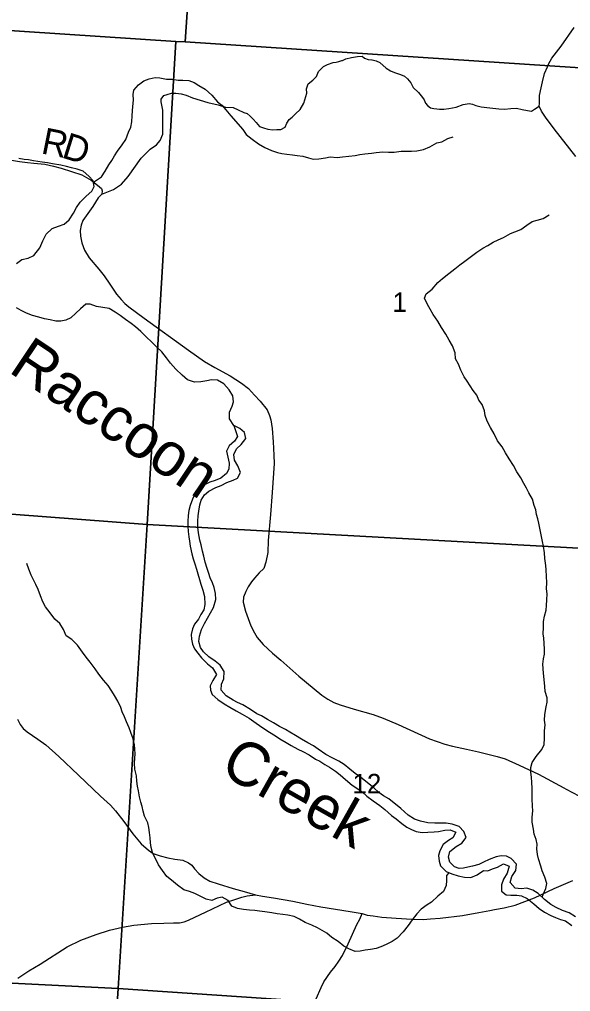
# Model space of a CAD drawing. Extents: x 0 to 34, y 0 to 22.
# Drawn here: x 25.453 to 26.642, y 16.992 to 19.088 of the extents above; entities that cross this region are included whole.
import ezdxf

# ---------------------------------------------------------------- set-up
doc = ezdxf.new("R2010")
doc.units = 0
for name, color, linetype in [('GM_X_Major_River', 7, 'Continuous'), ('GM_X_Major_River_Text', 7, 'Continuous'), ('GM_X_Minor_River', 7, 'Continuous'), ('GM_X_Section', 7, 'Continuous'), ('GM_X_Section_Text', 7, 'Continuous'), ('GM_X_State_Route', 7, 'Continuous'), ('GM_X_Township_Road', 7, 'Continuous'), ('GM_X_Township_Road_Text', 7, 'Continuous')]:
    doc.layers.add(name, color=color, linetype=linetype)

msp = doc.modelspace()

# ---------------------------------------------------------------- linework, layer by layer
at = {"layer": 'GM_X_Major_River'}
for points in [[(25.4467, 18.5616), (25.4589, 18.5707), (25.4721, 18.5732), (25.4843, 18.5792), (25.4973, 18.5958), (25.5035, 18.6109), (25.5108, 18.6249), (25.5242, 18.6373), (25.5378, 18.6422), (25.55, 18.6466), (25.5607, 18.6564), (25.5703, 18.6704), (25.5764, 18.6828), (25.5841, 18.6945), (25.5971, 18.7073), (25.6097, 18.7183), (25.6143, 18.7281), (25.6128, 18.7399), (25.6034, 18.7505), (25.5906, 18.7609), (25.5781, 18.7655), (25.566, 18.7683), (25.5546, 18.771), (25.5425, 18.7741), (25.5247, 18.7769), (25.5137, 18.7789), (25.5023, 18.7805), (25.4929, 18.7817), (25.4834, 18.7837), (25.4728, 18.7857), (25.4633, 18.7865), (25.452, 18.7885)], [(25.9162, 18.2126), (25.9068, 18.2267), (25.9069, 18.2411), (25.9123, 18.2539), (25.9154, 18.2638), (25.9136, 18.2767), (25.9057, 18.2893), (25.894, 18.3026), (25.8804, 18.3103), (25.8676, 18.3112), (25.8577, 18.309), (25.8448, 18.3064), (25.8311, 18.3058), (25.8163, 18.3112), (25.8047, 18.3211), (25.7907, 18.3341), (25.779, 18.3467), (25.7704, 18.3582), (25.7606, 18.3712), (25.7493, 18.3819), (25.7387, 18.3926), (25.7271, 18.404), (25.715, 18.4155), (25.7041, 18.4251), (25.6943, 18.4327), (25.6822, 18.4415), (25.6708, 18.4496), (25.6599, 18.4573), (25.6467, 18.4646), (25.633, 18.4673), (25.6194, 18.4689), (25.6061, 18.4743), (25.5963, 18.474), (25.5848, 18.4639), (25.5749, 18.4545), (25.5646, 18.4447), (25.5536, 18.4398), (25.5426, 18.4373), (25.5316, 18.4377), (25.5194, 18.4405), (25.5077, 18.4428), (25.4952, 18.4459), (25.4819, 18.4495), (25.4687, 18.4545), (25.457, 18.4603), (25.4468, 18.466)], [(26.4209, 17.2596), (26.4114, 17.2577), (26.4019, 17.2571), (26.392, 17.2609), (26.3822, 17.2709), (26.3789, 17.2811), (26.382, 17.294), (26.3954, 17.3042), (26.4079, 17.3113), (26.4175, 17.3237), (26.4119, 17.337), (26.4017, 17.3474), (26.3873, 17.3524), (26.3741, 17.3544), (26.3623, 17.3545), (26.3494, 17.3549), (26.3342, 17.3554), (26.3183, 17.3594), (26.3058, 17.3636), (26.2919, 17.3717), (26.2764, 17.3862), (26.25, 17.4069), (26.2387, 17.4138), (26.2288, 17.4211), (26.2179, 17.4307), (26.2081, 17.4387), (26.1892, 17.454), (26.1775, 17.4621), (26.1662, 17.4713), (26.1538, 17.4812), (26.1424, 17.4885), (26.1281, 17.4954), (26.1145, 17.5028), (26.0978, 17.5143), (26.088, 17.5215), (26.0756, 17.5277), (26.062, 17.5362), (26.0487, 17.5442), (26.037, 17.5511), (26.0272, 17.5565), (26.0143, 17.5631), (26.0015, 17.5711), (25.9886, 17.5784), (25.9754, 17.5865), (25.9656, 17.5907), (25.952, 17.5996), (25.9354, 17.6099), (25.924, 17.6149), (25.9142, 17.6203), (25.8991, 17.6295), (25.8889, 17.6418), (25.889, 17.6543), (25.8944, 17.6664), (25.8953, 17.6819), (25.8866, 17.6953), (25.8753, 17.7045), (25.8621, 17.7137), (25.8504, 17.7244), (25.844, 17.7339), (25.8403, 17.7465), (25.8419, 17.7582), (25.8462, 17.7722), (25.8527, 17.7854), (25.8592, 17.7968), (25.8657, 17.8085), (25.8719, 17.8198), (25.8769, 17.8372), (25.8766, 17.8498), (25.8737, 17.8631), (25.87, 17.8733), (25.8651, 17.8836), (25.8621, 17.8931), (25.8584, 17.9042), (25.8543, 17.9175), (25.8514, 17.9304), (25.848, 17.9418), (25.8455, 17.9551), (25.8425, 17.965), (25.84, 17.9813), (25.8385, 17.9935), (25.8382, 18.0064), (25.8391, 18.0174), (25.8403, 18.028), (25.8426, 18.0416), (25.8454, 18.0518), (25.8526, 18.0628), (25.8622, 18.0711), (25.8774, 18.0789), (25.8884, 18.0834), (25.901, 18.0898), (25.9143, 18.0946), (25.9238, 18.0991), (25.9303, 18.1112), (25.9247, 18.1252), (25.9176, 18.1374), (25.9162, 18.1503), (25.9219, 18.1621), (25.9319, 18.1715), (25.9418, 18.1847), (25.9392, 18.1972), (25.9291, 18.206)], [(25.9162, 18.2126), (25.9236, 18.1886), (25.9171, 18.1784)], [(25.9291, 18.206), (25.9162, 18.2126)], [(25.9171, 18.1784), (25.9061, 18.169), (25.9003, 18.1569), (25.9029, 18.144), (25.9062, 18.1311), (25.905, 18.1186), (25.9004, 18.1087), (25.8878, 18.099), (25.8756, 18.0937), (25.8638, 18.09), (25.8524, 18.0844), (25.8398, 18.0746), (25.831, 18.0633), (25.8264, 18.0535), (25.8218, 18.0403), (25.819, 18.0289), (25.8174, 18.0187), (25.8166, 18.0054), (25.8169, 17.9955), (25.8176, 17.9841), (25.819, 17.9727), (25.8201, 17.9629), (25.8219, 17.9526), (25.8252, 17.9359), (25.8282, 17.9249), (25.8319, 17.9142), (25.8353, 17.9028), (25.8386, 17.8925), (25.8419, 17.8804), (25.8449, 17.8701), (25.849, 17.8572), (25.8527, 17.8435), (25.8537, 17.8264), (25.851, 17.8151), (25.8449, 17.8045), (25.8395, 17.7946), (25.8311, 17.7837), (25.8268, 17.7739), (25.8241, 17.7614), (25.8244, 17.7515), (25.827, 17.7412), (25.8311, 17.7306), (25.8382, 17.7211), (25.8461, 17.7111), (25.859, 17.6981), (25.8699, 17.6897), (25.8785, 17.6752), (25.8705, 17.6624), (25.8651, 17.651), (25.8658, 17.6416), (25.8695, 17.632), (25.8812, 17.6213), (25.8948, 17.6125), (25.9076, 17.6048), (25.9209, 17.5971), (25.9337, 17.5902), (25.9492, 17.581), (25.9639, 17.5703), (25.9783, 17.5607), (25.9926, 17.5507), (26.0055, 17.5434), (26.0153, 17.5369), (26.0289, 17.5284), (26.0395, 17.5223), (26.0542, 17.5146), (26.0648, 17.5092), (26.0788, 17.5023), (26.092, 17.4931), (26.1018, 17.4884), (26.112, 17.4811), (26.1226, 17.4754), (26.1355, 17.4666), (26.1453, 17.4589), (26.157, 17.4486), (26.1713, 17.4367), (26.1811, 17.4302), (26.1932, 17.4217), (26.203, 17.4133), (26.2166, 17.403), (26.2309, 17.3926), (26.2419, 17.3842), (26.2562, 17.3716), (26.2664, 17.3643), (26.2785, 17.3543), (26.289, 17.3463), (26.2989, 17.3409), (26.3095, 17.337), (26.322, 17.3347), (26.3341, 17.3357), (26.3478, 17.3364), (26.3576, 17.3371), (26.3713, 17.34), (26.3827, 17.3407), (26.3948, 17.3356), (26.3886, 17.3228), (26.3791, 17.3172), (26.3673, 17.3085), (26.36, 17.2953), (26.3577, 17.2851), (26.3587, 17.2725), (26.3621, 17.263)], [(26.653, 17.1528), (26.6391, 17.1616), (26.6247, 17.1666), (26.6111, 17.1732), (26.5997, 17.179), (26.5858, 17.1904), (26.5722, 17.2031), (26.5609, 17.2104), (26.548, 17.2146), (26.5359, 17.2132), (26.523, 17.2148), (26.512, 17.2266), (26.5155, 17.2395), (26.5244, 17.2527), (26.5256, 17.266), (26.5143, 17.2782), (26.5045, 17.2836), (26.4927, 17.2841), (26.4817, 17.2819), (26.4665, 17.2763), (26.4547, 17.2707), (26.4448, 17.2658), (26.4307, 17.2618), (26.4209, 17.2596)], [(26.3621, 17.263), (26.3738, 17.2504), (26.3859, 17.2454), (26.4002, 17.2408), (26.4139, 17.238), (26.4275, 17.2379), (26.4408, 17.2435), (26.4546, 17.2525), (26.464, 17.2517), (26.4739, 17.2561), (26.4846, 17.2602), (26.4975, 17.267), (26.51, 17.2619), (26.5054, 17.2472), (26.4977, 17.234), (26.4934, 17.2219), (26.4933, 17.2082), (26.5035, 17.2005), (26.5134, 17.1993), (26.5263, 17.1992), (26.5365, 17.198), (26.5486, 17.1926), (26.5629, 17.1807), (26.575, 17.1704), (26.5863, 17.1627), (26.6, 17.1554), (26.6098, 17.1512), (26.6204, 17.1473), (26.6317, 17.1438), (26.645, 17.1338)]]:
    msp.add_lwpolyline(points, dxfattribs=at)
at = {"layer": 'GM_X_Minor_River'}
for points in [[(25.6131, 18.7376), (25.6307, 18.7487), (25.6386, 18.7613), (25.6465, 18.7746), (25.6525, 18.7841), (25.6586, 18.7939), (25.665, 18.8042), (25.6751, 18.8179), (25.6827, 18.8296), (25.6887, 18.8452), (25.6936, 18.8558), (25.6958, 18.8672), (25.6965, 18.8805), (25.6976, 18.8911), (25.6983, 18.9009), (25.6994, 18.9142), (25.699, 18.9263), (25.7005, 18.9358), (25.7103, 18.9472), (25.722, 18.956), (25.733, 18.9602), (25.7462, 18.9632), (25.7561, 18.9621), (25.7705, 18.9599), (25.7822, 18.9592), (25.7958, 18.9573), (25.806, 18.9573), (25.8185, 18.9566), (25.8303, 18.9521), (25.8405, 18.9457), (25.8538, 18.9377), (25.8682, 18.9252), (25.8804, 18.9109), (25.8903, 18.9033), (25.899, 18.8935), (25.9093, 18.8806), (25.9351, 18.8511), (25.9427, 18.8401), (25.9552, 18.8299), (25.9689, 18.8201), (25.9829, 18.8122), (25.9969, 18.8058), (26.0102, 18.8016), (26.0197, 18.799), (26.0303, 18.7979), (26.0428, 18.7964), (26.0526, 18.7949), (26.0651, 18.7934), (26.0772, 18.7897), (26.0871, 18.787), (26.0996, 18.7874), (26.1136, 18.7901), (26.1238, 18.7917), (26.1386, 18.7909), (26.1503, 18.7917), (26.1643, 18.7933), (26.1775, 18.7952), (26.1874, 18.7968), (26.1983, 18.7987), (26.2131, 18.8002), (26.2233, 18.8014), (26.2377, 18.8026), (26.2494, 18.8018), (26.2619, 18.8022), (26.2767, 18.8042), (26.2877, 18.8042), (26.2994, 18.8039), (26.3108, 18.805), (26.3251, 18.8077), (26.3391, 18.8138), (26.3539, 18.8222), (26.3648, 18.8245), (26.3773, 18.8313), (26.3894, 18.8355)], [(26.3642, 18.4241), (26.3562, 18.4377), (26.3463, 18.4521), (26.3395, 18.4635), (26.3334, 18.4733), (26.3273, 18.487), (26.3307, 18.4964), (26.3439, 18.5067), (26.3563, 18.5212), (26.3662, 18.5295), (26.3797, 18.5402), (26.3926, 18.5508), (26.4035, 18.5588), (26.4141, 18.5668), (26.4285, 18.5778), (26.4402, 18.5866), (26.4534, 18.5953), (26.464, 18.6007), (26.4753, 18.6083), (26.4863, 18.6132), (26.4976, 18.6182), (26.5127, 18.6269), (26.5225, 18.63), (26.5354, 18.6353), (26.5482, 18.6445), (26.5599, 18.6525), (26.5702, 18.6555), (26.583, 18.659), (26.5962, 18.667)], [(26.5811, 17.1948), (26.5836, 17.201), (26.5888, 17.2135), (26.5911, 17.2249), (26.5872, 17.2382), (26.5811, 17.2518), (26.5785, 17.2617), (26.5731, 17.278), (26.5708, 17.2874), (26.5696, 17.2992), (26.57, 17.3098), (26.5681, 17.3193), (26.5642, 17.3307), (26.5623, 17.3416), (26.5592, 17.3572), (26.5596, 17.3674), (26.5607, 17.3815), (26.5602, 17.3913), (26.5598, 17.4076), (26.5594, 17.4186), (26.5597, 17.4296), (26.5589, 17.4433), (26.5578, 17.4531), (26.557, 17.4653), (26.5566, 17.4751), (26.5596, 17.4854), (26.5682, 17.4983), (26.5803, 17.5135), (26.5852, 17.5241), (26.5859, 17.5381), (26.5858, 17.5541), (26.5873, 17.5669), (26.5858, 17.5768), (26.5872, 17.5889), (26.5898, 17.6056), (26.5917, 17.6155), (26.5917, 17.625), (26.5875, 17.639), (26.5867, 17.6496), (26.5851, 17.6644), (26.5839, 17.678), (26.5823, 17.6978), (26.5838, 17.7095), (26.5861, 17.719), (26.5864, 17.7296), (26.5856, 17.7429), (26.5844, 17.7535), (26.5836, 17.763), (26.584, 17.7766), (26.5843, 17.7895), (26.5858, 17.8009), (26.5899, 17.8142), (26.5903, 17.8244), (26.591, 17.8362), (26.5917, 17.8495), (26.5905, 17.8601), (26.5909, 17.8741), (26.5908, 17.8866), (26.59, 17.901), (26.5888, 17.9105), (26.5869, 17.9253), (26.5865, 17.9382), (26.5842, 17.9522), (26.5819, 17.9624), (26.5796, 17.9734), (26.5742, 18.0015), (26.5719, 18.0109), (26.5692, 18.0208), (26.5673, 18.0306), (26.5642, 18.0401), (26.56, 18.0534), (26.552, 18.067), (26.547, 18.0772), (26.5417, 18.0871), (26.5349, 18.0996), (26.5265, 18.1128), (26.5193, 18.1261), (26.5097, 18.1405), (26.5017, 18.1537), (26.4949, 18.1666), (26.4846, 18.1795), (26.4778, 18.1942), (26.4698, 18.2082), (26.4622, 18.2219), (26.4583, 18.2344), (26.4564, 18.2442), (26.4518, 18.2575), (26.4442, 18.2673), (26.4404, 18.2783), (26.432, 18.2882), (26.426, 18.298), (26.4195, 18.3078), (26.4126, 18.3177), (26.4058, 18.3321), (26.4008, 18.345), (26.3943, 18.3563), (26.3932, 18.3696), (26.3878, 18.384), (26.3802, 18.3965), (26.3734, 18.4097), (26.3642, 18.4241)], [(25.5483, 17.7722), (25.5403, 17.7854), (25.5297, 17.7945), (25.5194, 17.8081), (25.5095, 17.8214), (25.5042, 17.832), (25.4985, 17.8449), (25.4935, 17.8585), (25.4889, 17.8699), (25.484, 17.8797), (25.479, 17.8899), (25.4737, 17.9024), (25.4691, 17.9149)], [(26.3798, 17.2479), (26.3749, 17.2422), (26.3745, 17.2308), (26.3742, 17.2202), (26.3685, 17.2073), (26.3561, 17.1974), (26.3425, 17.1841), (26.3327, 17.1784), (26.3198, 17.1689), (26.3108, 17.1594), (26.301, 17.1465), (26.2919, 17.1343), (26.281, 17.1203), (26.2686, 17.107), (26.2576, 17.0997), (26.2448, 17.0933), (26.233, 17.0883), (26.2232, 17.0841), (26.2111, 17.0825), (26.1994, 17.081), (26.1888, 17.0787), (26.1778, 17.0783), (26.1638, 17.084), (26.1535, 17.0892), (26.141, 17.0994), (26.1277, 17.1081), (26.1164, 17.1176), (26.1065, 17.1232), (26.0963, 17.1293), (26.0841, 17.1346), (26.0697, 17.1402), (26.0576, 17.1478), (26.0462, 17.1534), (26.0322, 17.1561), (26.0216, 17.1575), (26.0095, 17.1594), (25.9977, 17.1613), (25.9826, 17.1635), (25.9712, 17.165), (25.9614, 17.1661), (25.9496, 17.1672), (25.9371, 17.1687), (25.9239, 17.1706), (25.9114, 17.1759), (25.9038, 17.188), (25.8905, 17.1948), (25.8799, 17.1928), (25.8686, 17.1883), (25.8564, 17.1905), (25.8432, 17.1973), (25.8318, 17.2033), (25.8204, 17.2071), (25.8079, 17.2109), (25.7943, 17.2211), (25.7817, 17.2317), (25.7715, 17.2396), (25.762, 17.2525), (25.7536, 17.265), (25.7403, 17.2915), (25.7376, 17.3021), (25.736, 17.3123), (25.7356, 17.3229), (25.7341, 17.3347), (25.7322, 17.3453), (25.7302, 17.3555), (25.7234, 17.3695), (25.7203, 17.3809), (25.718, 17.3908), (25.7153, 17.4002), (25.7126, 17.4112), (25.7099, 17.4245), (25.708, 17.4343), (25.7065, 17.445), (25.7057, 17.4567), (25.7026, 17.4711), (25.7014, 17.4844), (25.7025, 17.495), (25.7029, 17.5045), (25.7025, 17.5143), (25.7013, 17.5238), (25.699, 17.5367), (25.6936, 17.5503), (25.6898, 17.5602), (25.6845, 17.5731), (25.6803, 17.5841), (25.6749, 17.5947), (25.6723, 17.6045), (25.6658, 17.6178), (25.6585, 17.6299), (25.6525, 17.6397), (25.6445, 17.6518), (25.635, 17.6632), (25.6247, 17.6764), (25.6171, 17.6878), (25.6057, 17.7018), (25.5977, 17.7128), (25.5893, 17.7234), (25.5783, 17.7385), (25.5662, 17.751), (25.5544, 17.7589), (25.5483, 17.7722)]]:
    msp.add_lwpolyline(points, dxfattribs=at)
at = {"layer": 'GM_X_Section'}
for points in [[(25.8788, 20.042), (25.8109, 19.0399), (25.7909, 19.041), (24.8107, 19.1055), (24.8672, 20.1076)], [(25.8788, 20.042), (26.893, 19.9764), (26.8274, 18.9732), (25.8109, 19.0399)], [(24.788, 19.1066), (24.8107, 19.1055), (25.7909, 19.041), (25.7287, 17.9991), (24.7175, 18.0761)], [(25.7909, 19.041), (25.8109, 19.0399), (26.8274, 18.9732), (26.7513, 17.9427), (25.7287, 17.9991)], [(25.7287, 17.9991), (25.6662, 16.9982), (24.6497, 17.049), (24.7175, 18.0761)], [(25.7287, 17.9991), (26.7513, 17.9427), (26.6773, 16.93), (25.6662, 16.9982)], [(24.6497, 17.049), (25.6662, 16.9982), (25.5991, 15.9654), (24.5822, 16.0431)], [(25.6662, 16.9982), (26.6773, 16.93), (26.6015, 15.9112), (25.5991, 15.9654)]]:
    msp.add_lwpolyline(points, close=True, dxfattribs=at)
at = {"layer": 'GM_X_State_Route'}
msp.add_lwpolyline([(26.0934, 16.9755), (26.1042, 17.0002), (26.1099, 17.0127), (26.1242, 17.0332), (26.1342, 17.0456), (26.1424, 17.0569), (26.1506, 17.069), (26.1623, 17.0943), (26.181, 17.1365), (26.1876, 17.148), (26.1928, 17.1602), (26.2033, 17.1566), (26.2168, 17.155), (26.2355, 17.1521), (26.2663, 17.1495), (26.2998, 17.1475), (26.3244, 17.1473), (26.3404, 17.1484), (26.3614, 17.1495), (26.409, 17.1559), (26.4446, 17.1621), (26.4683, 17.1662), (26.4784, 17.1682), (26.4993, 17.1723), (26.5231, 17.1781), (26.5645, 17.194), (26.6072, 17.2138), (26.6476, 17.2309)], dxfattribs=at)
at = {"layer": 'GM_X_Township_Road'}
for points in [[(26.5745, 18.9014), (26.5751, 18.9068), (26.5751, 18.911), (26.5753, 18.9243), (26.5793, 18.941), (26.5821, 18.9541), (26.5861, 18.9719), (26.5923, 18.9861), (26.5947, 18.9916), (26.6021, 19.0046), (26.622, 19.0304), (26.6503, 19.0713)], [(25.6313, 18.7112), (25.6561, 18.7213), (25.6738, 18.7333), (25.6883, 18.7499), (25.7161, 18.7894), (25.7354, 18.8083), (25.7488, 18.8177), (25.7571, 18.8272), (25.7627, 18.8407), (25.7627, 18.877), (25.7631, 18.8927), (25.7588, 18.9107), (25.7592, 18.9162), (25.7647, 18.9242), (25.7718, 18.9268), (25.7817, 18.9293), (25.7909, 18.9293), (25.8024, 18.9281), (25.8132, 18.9249), (25.8268, 18.9192), (25.8599, 18.9095), (25.8818, 18.904), (25.8979, 18.8994), (25.9142, 18.8982), (25.9255, 18.8932), (25.9372, 18.8877), (25.9448, 18.8854), (25.9515, 18.8794), (25.9577, 18.8734), (25.9644, 18.8663), (25.9715, 18.8577), (25.98, 18.8545), (25.989, 18.8515), (25.9998, 18.8502), (26.0085, 18.8513), (26.0175, 18.8511), (26.0269, 18.8559), (26.0306, 18.8649), (26.0354, 18.8729), (26.0417, 18.8775), (26.0486, 18.8847), (26.0589, 18.8941), (26.0672, 18.9081), (26.0732, 18.9295), (26.0727, 18.9387), (26.0764, 18.9498), (26.0867, 18.9574), (26.0941, 18.9656), (26.0989, 18.9764), (26.1097, 18.9866), (26.1178, 18.9912), (26.13, 18.9953), (26.1367, 18.9965), (26.1424, 18.9978), (26.1491, 18.9997)], [(26.1491, 18.9997), (26.15, 18.9999), (26.1578, 19.0031), (26.1696, 19.0066), (26.1824, 19.0082), (26.193, 19.0089), (26.1981, 19.005), (26.2057, 19.002), (26.2137, 19.0011), (26.2146, 19.0009)], [(26.2146, 19.0009), (26.2227, 18.9992), (26.231, 18.9957), (26.2448, 18.9836), (26.254, 18.9774), (26.2627, 18.9739), (26.2756, 18.9698), (26.2839, 18.9659), (26.2903, 18.9606), (26.2975, 18.9518), (26.3025, 18.9417), (26.3143, 18.9311), (26.323, 18.9203), (26.3264, 18.9148), (26.3297, 18.9081), (26.3338, 18.9026), (26.34, 18.8978), (26.3471, 18.8964), (26.3536, 18.8952), (26.3596, 18.8948), (26.3688, 18.895), (26.3796, 18.8964), (26.3955, 18.8989), (26.4109, 18.9047), (26.4233, 18.9074), (26.4311, 18.9058), (26.4378, 18.9028), (26.4493, 18.8996), (26.4679, 18.8978), (26.4875, 18.8959), (26.4997, 18.895), (26.5135, 18.8966), (26.5254, 18.8971), (26.5379, 18.8941), (26.5494, 18.8918), (26.5579, 18.8906), (26.5648, 18.8948), (26.5745, 18.9014)], [(26.6539, 18.7931), (26.6068, 18.8527), (26.588, 18.8778), (26.5797, 18.8906), (26.5745, 18.9014)], [(25.4366, 18.7848), (25.4534, 18.7816), (25.4705, 18.7795), (25.4847, 18.7782), (25.5082, 18.7759), (25.5271, 18.7722), (25.5436, 18.7676), (25.5655, 18.7607), (25.588, 18.7535), (25.608, 18.7416), (25.6218, 18.731), (25.6301, 18.7239), (25.6322, 18.719), (25.6313, 18.7112), (25.6232, 18.7034), (25.6117, 18.685), (25.597, 18.6647), (25.5901, 18.6544), (25.5864, 18.6443), (25.5843, 18.6332), (25.5848, 18.6208), (25.588, 18.6068), (25.594, 18.5907), (25.6039, 18.5743), (25.6244, 18.5495), (25.6363, 18.5355), (25.6487, 18.5175), (25.6628, 18.4961), (25.6727, 18.4846), (25.6809, 18.4754), (25.6897, 18.4683), (25.7224, 18.4441), (25.8178, 18.3749), (25.8523, 18.3505), (25.8749, 18.3374), (25.9078, 18.3194), (25.9324, 18.304), (25.9473, 18.2921), (25.9607, 18.2778), (25.9729, 18.2647), (25.9876, 18.2465), (25.9929, 18.2343), (25.9954, 18.2244), (25.9984, 18.206), (26.001, 18.177), (26.0025, 18.1483), (26.0028, 18.1304), (25.9986, 18.068), (25.995, 18.0206), (25.9901, 17.9643), (25.989, 17.9387), (25.9851, 17.918), (25.9809, 17.9042), (25.9706, 17.8946), (25.9605, 17.8835), (25.954, 17.8755), (25.9471, 17.8642), (25.9418, 17.8543), (25.937, 17.8421), (25.9361, 17.8318), (25.941, 17.8122), (25.9471, 17.7961), (25.9528, 17.7807), (25.9602, 17.7653), (25.9659, 17.7549), (25.979, 17.7401), (25.9995, 17.7218), (26.0173, 17.7063), (26.0565, 17.6719), (26.1055, 17.6309), (26.1189, 17.6223), (26.1317, 17.6153), (26.1451, 17.6102), (26.1755, 17.6009), (26.2162, 17.5893), (26.238, 17.5813), (26.2701, 17.5678), (26.3381, 17.5367), (26.3713, 17.5249), (26.3878, 17.5207), (26.4182, 17.5141), (26.4435, 17.5086), (26.4843, 17.4989), (26.5012, 17.4936), (26.5316, 17.4799), (26.573, 17.4605), (26.6276, 17.4308)], [(25.4491, 17.5789), (25.4552, 17.5676), (25.4616, 17.5591), (25.4704, 17.5519), (25.4934, 17.536), (25.5101, 17.5235), (25.5383, 17.4982), (25.581, 17.4583), (25.6284, 17.4129), (25.6495, 17.3935), (25.6604, 17.3811), (25.6784, 17.3584), (25.6978, 17.3314), (25.7158, 17.31), (25.7317, 17.2963), (25.7418, 17.2895), (25.7568, 17.284), (25.7733, 17.2802), (25.7887, 17.2773), (25.8056, 17.2748), (25.8183, 17.2693), (25.8254, 17.2641), (25.8311, 17.2565), (25.8404, 17.2461), (25.8518, 17.2368), (25.8638, 17.23), (25.8823, 17.2238), (25.9145, 17.2141), (25.938, 17.2077), (25.9628, 17.1999)], [(26.6276, 17.4308), (26.6328, 17.4279), (26.6602, 17.414), (26.6971, 17.3955)], [(25.4501, 17.0205), (25.4736, 17.0366), (25.4981, 17.0505), (25.5561, 17.0878), (25.586, 17.1026), (25.6187, 17.1147), (25.6478, 17.1242), (25.6759, 17.1302), (25.7, 17.1349), (25.7381, 17.1382), (25.765, 17.1393), (25.786, 17.14), (25.7988, 17.14), (25.809, 17.142), (25.818, 17.1457), (25.8319, 17.152), (25.8547, 17.163), (25.9003, 17.184), (25.9178, 17.1903), (25.9331, 17.1952), (25.9448, 17.1979), (25.9628, 17.1999), (25.9776, 17.1972), (26.0015, 17.194), (26.0432, 17.1862), (26.0733, 17.1802)], [(26.0733, 17.1802), (26.1035, 17.1742), (26.1666, 17.1643), (26.1928, 17.1602)]]:
    msp.add_lwpolyline(points, dxfattribs=at)

# ---------------------------------------------------------------- texts
at = {"layer": 'GM_X_Major_River_Text'}
for s, rotation, p in [('Raccoon', 326.2028, (25.4274, 18.3293)), ('Creek', 330.5751, (25.8824, 17.464))]:
    msp.add_text(s, height=0.0947, rotation=rotation, dxfattribs=at).set_placement(p)
at = {"layer": 'GM_X_Section_Text'}
for s, height, p in [('1', 0.0419, (26.2582, 18.4576)), ('12', 0.04186, (26.1719, 17.4192))]:
    msp.add_text(s, height=height, rotation=0, dxfattribs=at).set_placement(p)
at = {"layer": 'GM_X_Township_Road_Text'}
for s, rotation, p in [('R', 348.6265, (25.4981, 18.7999)), ('D', 342.6629, (25.5423, 18.7911))]:
    msp.add_text(s, height=0.0568, rotation=rotation, dxfattribs=at).set_placement(p)

doc.saveas('drawing.dxf')
